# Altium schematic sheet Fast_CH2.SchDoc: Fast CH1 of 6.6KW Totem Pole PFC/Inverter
size A4
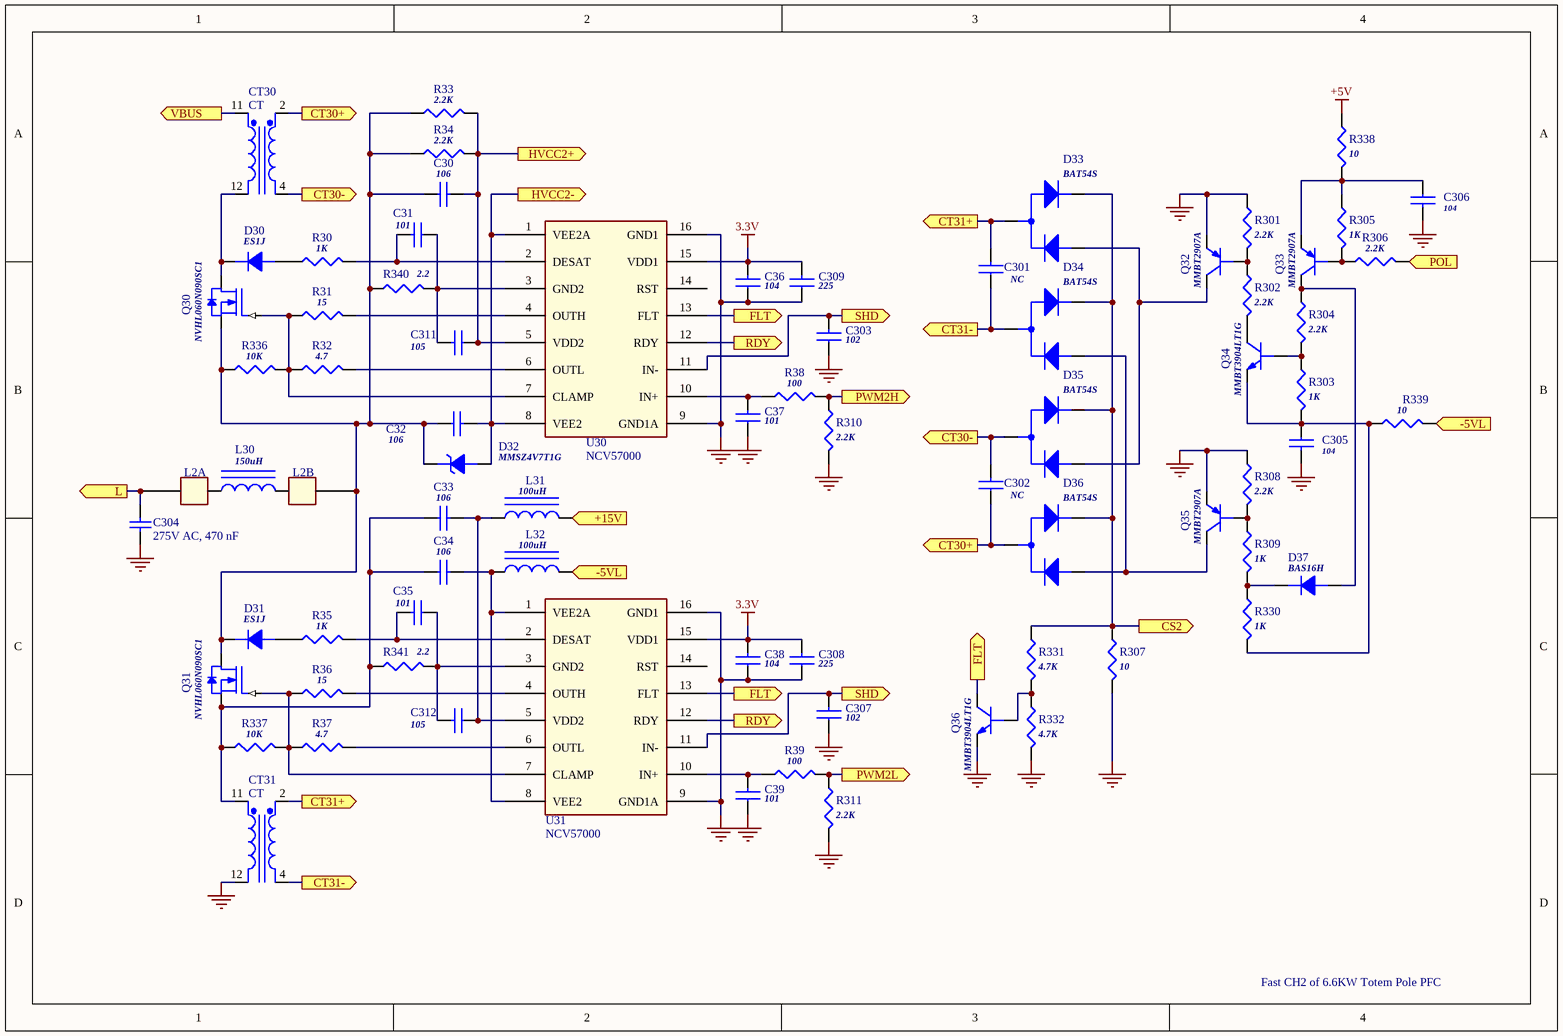
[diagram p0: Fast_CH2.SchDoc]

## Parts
C30  106  [SMT_1206_CM]
C31  101  [SMT_0805_CM]
C32  106  [SMT_1206_CM]
C33  106  [SMT_1206_CM]
C34  106  [SMT_1206_CM]
C35  101  [SMT_0805_CM]
C36  104  [SMT_0805_CM]
C37  101  [SMT_0805_CM]
C38  104  [SMT_0805_CM]
C39  101  [SMT_0805_CM]
C301  NC  [SMT_0805_CM]
C302  NC  [SMT_0805_CM]
C303  102  [SMT_0805_CM]
C304  275V AC, 470 nF  [WCAP-FTX2_18x8x14_CS]
C305  104  [SMT_0805_CM]
C306  104  [SMT_0805_CM]
C307  102  [SMT_0805_CM]
C308  225  [SMT_0805_CM]
C309  225  [SMT_0805_CM]
C311  105  [SMT_0805_CM]
C312  105  [SMT_0805_CM]
CT30  CT  [CT_EE13]
CT31  CT  [CT_EE13]
D30  ES1J  [DO-214AC(SMA)]
D31  ES1J  [DO-214AC(SMA)]
D32  MMSZ4V7T1G  [SOD-123FL]
D33  BAT54S  [SOT-23-3L]
D34  BAT54S  [SOT-23-3L]
D35  BAT54S  [SOT-23-3L]
D36  BAT54S  [SOT-23-3L]
D37  BAS16H  [SOD-323M]
L2A  (no value)  [TermL]
L2B  (no value)  [TermL]
L30  150uH  [INDUCTOR-7*7*3.5]
L31  100uH  [Bead_1210]
L32  100uH  [Bead_1210]
Q30  NVHL060N090SC1  [TO247]
Q31  NVHL060N090SC1  [TO247]
Q32  MMBT2907A  [SOT-23-3L]
Q33  MMBT2907A  [SOT-23-3L]
Q34  MMBT3904LT1G  [SOT-23-3L]
Q35  MMBT2907A  [SOT-23-3L]
Q36  MMBT3904LT1G  [SOT-23-3L]
R30  1K  [SMT_0805_RM]
R31  15  [SMT_1206_RM]
R32  4.7  [SMT_1206_RM]
R33  2.2K  [SMT_1206_RM]
R34  2.2K  [SMT_1206_RM]
R35  1K  [SMT_0805_RM]
R36  15  [SMT_1206_RM]
R37  4.7  [SMT_1206_RM]
R38  100  [SMT_0805_RM]
R39  100  [SMT_0805_RM]
R301  2.2K  [SMT_0805_RM]
R302  2.2K  [SMT_0805_RM]
R303  1K  [SMT_0805_RM]
R304  2.2K  [SMT_0805_RM]
R305  1K  [SMT_0805_RM]
R306  2.2K  [SMT_0805_RM]
R307  10  [SMT_1206_RM]
R308  2.2K  [SMT_0805_RM]
R309  1K  [SMT_0805_RM]
R310  2.2K  [SMT_0805_RM]
R311  2.2K  [SMT_0805_RM]
R330  1K  [SMT_1206_RM]
R331  4.7K  [SMT_0805_RM]
R332  4.7K  [SMT_0805_RM]
R336  10K  [SMT_0805_RM]
R337  10K  [SMT_0805_RM]
R338  10  [SMT_0805_RM]
R339  10  [SMT_0805_RM]
R340  2.2  [SMT_0805_RM]
R341  2.2  [SMT_0805_RM]
U30  NCV57000  [SOP16W]
U31  NCV57000  [SOP16W]

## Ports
+15V (out), -5VL (out), CS2 (out), CT30+ (out), CT30- (out), CT31+ (out), CT31- (out), FLT (out), HVCC2+ (out), HVCC2- (out), L (out), POL (out), PWM2H (out), PWM2L (out), RDY (out), SHD (out), VBUS (out)

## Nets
3.3V: C36.2 C38.2 C308.2 C309.2 U30.15(VDD1) U31.15(VDD1)
+5V: R338.1
PGND: C36.1 C37.1 C38.1 C39.1 C303.1 C304.2 C305.2 C306.2 C307.1 C308.1 C309.1 CT31.12(Pri-) Q32.2(E) Q35.2(E) Q36.2(E) R301.1 R307.2 R308.1 R310.2 R311.2 R332.2 U30.9(GND1A) U30.16(GND1) U31.9(GND1A) U31.16(GND1)
+15V: L31.2 ; port +15V
-5VL: L32.2 R339.2 ; port -5VL
CS2: D33.2 D34.2 D35.2 D36.2 R307.1 R331.1 ; port CS2
CT30+: C302.1 CT30.2(Sec+) D36.3 ; port CT30+
CT30-: C302.2 CT30.4(Sec-) D35.3 ; port CT30-
CT31+: C301.2 CT31.2(Sec+) D33.3 ; port CT31+
CT31-: C301.1 CT31.4(Sec-) D34.3 ; port CT31-
FLT: Q36.3(C) U30.13(FLT) U31.13(FLT) ; port FLT
HVCC2+: C30.2 C311.1 R33.2 R34.2 U30.5(VDD2) ; port HVCC2+
HVCC2-: C32.2 D32.1(ANODE) U30.1(VEE2A) U30.8(VEE2) ; port HVCC2-
L: C304.1 L2A.1 ; port L
POL: R306.2 ; port POL
PWM2H: R38.2 R310.1 ; port PWM2H
PWM2L: R39.2 R311.1 ; port PWM2L
RDY: U30.12(RDY) U31.12(RDY) ; port RDY
SHD: C303.2 C307.2 U30.11(IN-) U31.11(IN-) ; port SHD
VBUS: CT30.11(Pri+) ; port VBUS
NetC30_1: C30.1 C32.1 D31.2(K) D32.2(CATHODE) L2B.1 Q30.3(SOURCE) Q31.2(DRAIN) R33.1 R34.1 R336.1 R340.1
NetC31_1: C31.1 C311.2 R340.2 U30.3(GND2)
NetC31_2: C31.2 R30.2 U30.2(DESAT)
NetC33_1: C33.1 C34.1 CT31.11(Pri+) Q31.3(SOURCE) R337.1 R341.1
NetC33_2: C33.2 C312.1 L31.1 U31.5(VDD2)
NetC34_2: C34.2 L32.1 U31.1(VEE2A) U31.8(VEE2)
NetC35_1: C35.1 C312.2 R341.2 U31.3(GND2)
NetC35_2: C35.2 R35.2 U31.2(DESAT)
NetC37_2: C37.2 R38.1 U30.10(IN+)
NetC39_2: C39.2 R39.1 U31.10(IN+)
NetC305_1: C305.1 Q34.2(E) R303.2 R330.2 R339.1
NetC306_1: C306.1 Q33.2(E) R305.1 R338.2
NetCT30_12: CT30.12(Pri-) D30.2(K) Q30.2(DRAIN)
NetD30_1: D30.1(A) R30.1
NetD31_1: D31.1(A) R35.1
NetD33_1: D33.1 D35.1 Q32.3(C)
NetD34_1: D34.1 D36.1 Q35.3(C)
NetD37_1: D37.1(A) Q33.3(C) R304.1
NetD37_2: D37.2(K) R309.2 R330.1
NetQ30_1: Q30.1(GATE) R31.1 R32.1 R336.2 U30.7(CLAMP)
NetQ31_1: Q31.1(GATE) R36.1 R37.1 R337.2 U31.7(CLAMP)
NetQ32_1: Q32.1(B) R301.2 R302.1
NetQ33_1: Q33.1(B) R305.2 R306.1
NetQ34_1: Q34.1(B) R303.1 R304.2
NetQ34_3: Q34.3(C) R302.2
NetQ35_1: Q35.1(B) R308.2 R309.1
NetQ36_1: Q36.1(B) R331.2 R332.1
NetR31_2: R31.2 U30.4(OUTH)
NetR32_2: R32.2 U30.6(OUTL)
NetR36_2: R36.2 U31.4(OUTH)
NetR37_2: R37.2 U31.6(OUTL)

Not connected (* = marked no-connect by the designer): L30 1 2; U30 14(RST); U31 14(RST)

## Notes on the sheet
- Fast CH2 of 6.6KW Totem Pole PFC

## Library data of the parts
C30-C35 C301 C302 = CAP_1206
C36-C39 C303 C307-C309 C311 C312 = CAP_0805
C304 = 890324025039CS: WCAP-FTX2 Film Capacitors, 18x8x14mm, 275V AC, 470 nF; Rated Voltage: 275V AC; Value: 470 nF
C305 C306 = CAP NP
CT30 CT31 = Trans Cupl: Transformer (Coupled Inductor Model)
D30 D31 = D_SMA(DO-214AC)
D32 = DIODE ZENER
D33-D36 = BAT54S/SOT
D37 = DIODE
L2A L2B = P_1
L30-L32 = INDUCTOR IRON
Q30 Q31 = SICMOS
Q32 Q33 Q35 = Q_PNP_SOT-23-3L
Q34 Q36 = Q_NPN_SOT-23-3L
R30-R39 R306 R336 R337 R339-R341 = R_0805
R301-R305 R307-R311 R330-R332 R338 = R
U30 U31 = U_NCV57000_SO-16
